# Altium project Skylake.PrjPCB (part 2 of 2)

## Sheet Skylake_TPS22993_U7.SchDoc
size 431 x 279 mm; Date: Not shown in title block; ApprovedBy: Not shown in title block; CheckedBy: Not shown in title block; Author: Not shown in title block; CompanyName: Not shown in title block; Engineer: Not shown in title block; Organization: Not shown in title block; Address1: Not shown in title block; Address2: Not shown in title block; Address3: Not shown in title block; Address4: Not shown in title block; DocumentNumber: 1; Revision: Use project parameter SCH_Rev; SheetNumber: 7; SheetTotal: 9; PageSetup: Record=PageOptions|CenterHorizontal=True|CenterVertical=True|PrintScale=1.00|XCorrection=1.00|YCorrection=1.00|PrintKind=0|BorderSize=5000000|LeftOffset=0|BottomOffset=0|Orientation=2|PaperLength=1000|PaperWidth=1000|Scale=100|PaperSource=15|PrintQuality=600|MediaType=1|DitherType=10|PaperKind=Letter|PrintScaleMode=1
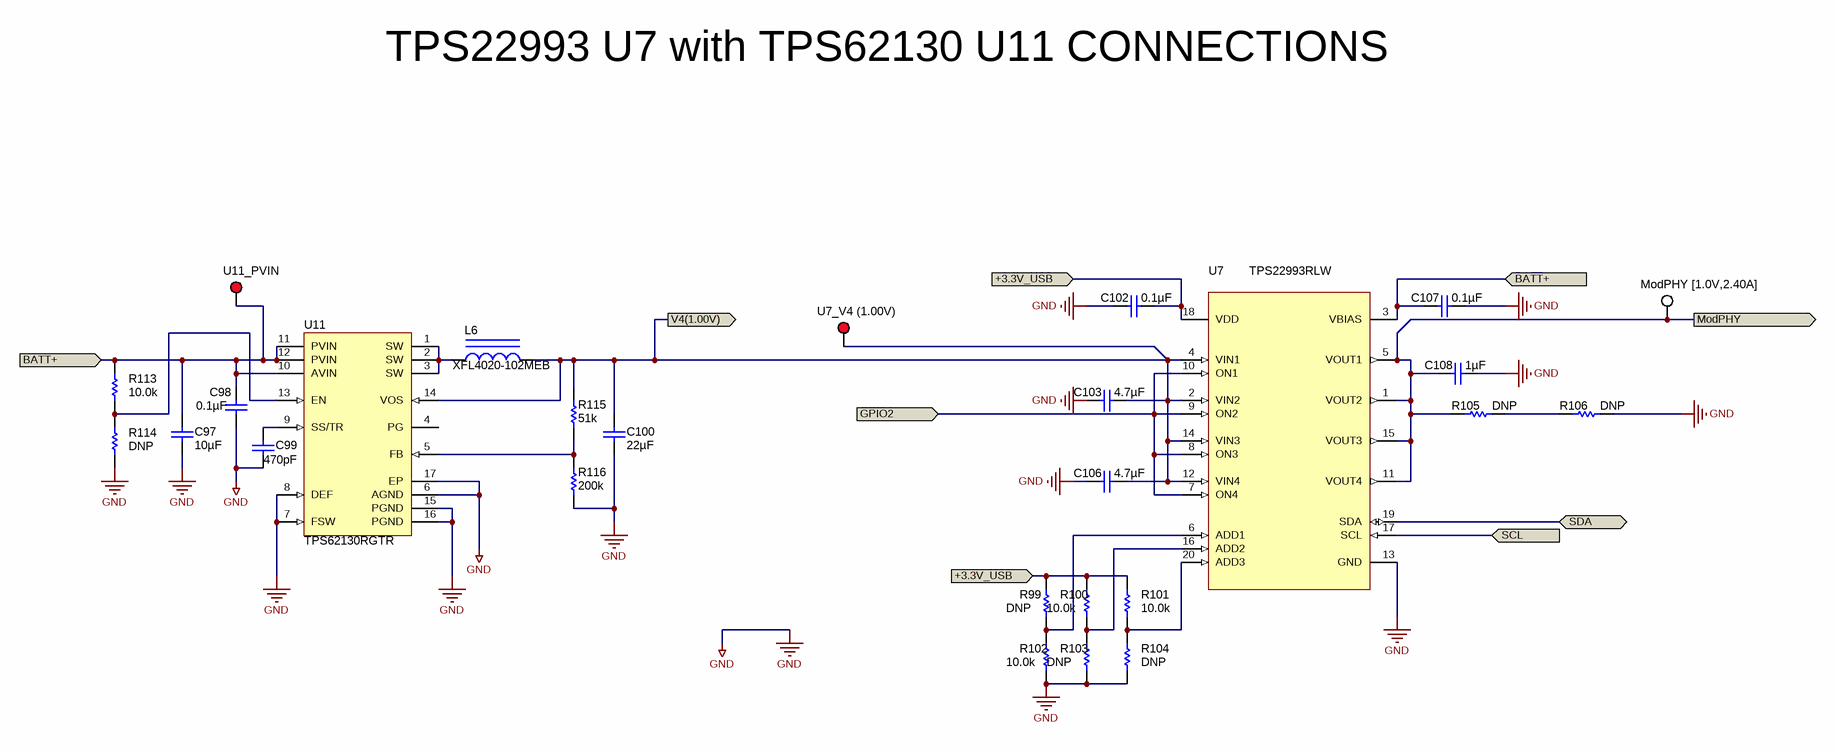
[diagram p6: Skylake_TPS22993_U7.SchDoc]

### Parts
C97  ValueDisplayed: 10µF  [0805_HV]  (hidden comment: C2012JB1V106K085AC)
C98  ValueDisplayed: 0.1µF  [0805_HV]  (hidden comment: 08055C104JAT2A)
C99  ValueDisplayed: 470pF  [0603]  (hidden comment: C0603C471K5RACTU)
C100  ValueDisplayed: 22µF  [0805_HV]  (hidden comment: LMK212BJ226MG-T)
C102  ValueDisplayed: 0.1µF  [0603]  (hidden comment: C0603C104K8RACTU)
C103  ValueDisplayed: 4.7µF  [0603]  (hidden comment: GRM188R60J475KE19D)
C106  ValueDisplayed: 4.7µF  [0603]  (hidden comment: GRM188R60J475KE19D)
C107  ValueDisplayed: 0.1µF  [0805_HV]  (hidden comment: GMK212BJ104KGHT)
C108  ValueDisplayed: 1µF  [0603]  (hidden comment: C0603C105K8PACTU)
L6  XFL4020-102MEB  [XFL4020]
ModPHY_[1.0V,2.40A]  5007  [Keystone5007]  (value not drawn)
R99  value DNP  [0402]  (hidden comment: CRCW040210K0FKED)
R100  value 10.0k  [0402]  (hidden comment: CRCW040210K0FKED)
R101  value 10.0k  [0402]  (hidden comment: CRCW040210K0FKED)
R102  value 10.0k  [0402]  (hidden comment: CRCW040210K0FKED)
R103  value DNP  [0402]  (hidden comment: CRCW040210K0FKED)
R104  value DNP  [0402]  (hidden comment: CRCW040210K0FKED)
R105  value DNP  [2512M]  (hidden comment: RLP73K3AR20JTE)
R106  value DNP  [2512M]  (hidden comment: RLP73K3AR22JTE)
R113  value 10.0k  [0402]  (hidden comment: CRCW040210K0FKED)
R114  value DNP  [0402]  (hidden comment: CRCW040210K0FKED)
R115  value 51k  [0603]  (hidden comment: CRCW060351K0JNEA)
R116  value 200k  [0603]  (hidden comment: CRCW0603200KFKEA)
U7  TPS22993RLW  [RLW0020A]
U7_V4_(1.00V)  5005  [Keystone5005]  (value not drawn)
U11  TPS62130RGTR  [RGT0016C]
U11_PVIN  5005  [Keystone5005]  (value not drawn)

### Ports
+3.3V_USB (in), BATT+ (in), GPIO2 (in), ModPHY (out), SCL (in), SDA (bidir), V4(1.00V) (out)

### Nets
GND: C97.2 C98.2 C99.2 C100.2 C102.2 C103.2 C106.2 C107.1 C108.1 R102.1 R103.1 R104.1 R106.2 R114.1 R116.1 U7.13(GND) U11.6(AGND) U11.7(FSW) U11.8(DEF) U11.15(PGND) U11.16(PGND) U11.17(EP)
+3.3V_USB: C102.1 R99.2 R100.2 R101.2 U7.18(VDD) ; port +3.3V_USB
BATT+: C97.1 C98.1 C107.2 R113.2 U7.3(VBIAS) U11.10(AVIN) U11.11(PVIN) U11.12(PVIN) U11_PVIN.1 ; port BATT+
GPIO2: U7.7(ON4) U7.8(ON3) U7.9(ON2) U7.10(ON1) ; port GPIO2
ModPHY: C108.2 ModPHY_[1.0V,2.40A].1 R105.1 U7.1(VOUT2) U7.5(VOUT1) U7.11(VOUT4) U7.15(VOUT3) ; port ModPHY
SCL: U7.17(SCL) ; port SCL
SDA: U7.19(SDA) ; port SDA
V4(1.00V): C100.1 C103.1 C106.1 L6.2 R115.2 U7.2(VIN2) U7.4(VIN1) U7.12(VIN4) U7.14(VIN3) U7_V4_(1.00V).1 U11.14(VOS) ; port V4(1.00V)
NetC99_1: C99.1 U11.9(SS/TR)
NetL6_1: L6.1 U11.1(SW) U11.2(SW) U11.3(SW)
NetR99_1: R99.1 R102.2 U7.6(ADD1)
NetR100_1: R100.1 R103.2 U7.16(ADD2)
NetR101_1: R101.1 R104.2 U7.20(ADD3)
NetR105_2: R105.2 R106.1
NetR113_1: R113.1 R114.2 U11.13(EN)
NetR115_1: R115.1 R116.2 U11.5(FB)

Not connected (* = marked no-connect by the designer): U11 4(PG)

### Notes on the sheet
- TPS22993 U7 with TPS62130 U11 CONNECTIONS

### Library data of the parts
C97 = GRM21BR61E226ME44: CAP, CERM, 10uF, 35V, +/-10%, X5R, 0805; Manufacturer: TDK Corporation; Polarized: N; CompType: Capacitor; U/M: EA; Cap_F: 0.000022; Tolerance_%: 20; Value1: Unknown; VDC_V: 35; TaMin_C: -55; TaMax_C: 85; Cap_Case: 0805
C98 = 08055C104JAT2A: CAP, CERM, 0.1uF, 50V, +/-5%, X7R, 0805; Manufacturer: AVX; Polarized: N; CompType: Capacitor; U/M: EA; Cap_F: 0.0000001; Tolerance_%: 5; ESR_Ohm: 0.024; Value1: 0.024 ohm; VDC_V: 50; TaMin_C: -55; TaMax_C: 125; Cap_Case: 0805
C99 = C0603C471K5RACTU: CAP, CERM, 470pF, 50V, +/-10%, X7R, 0603; Manufacturer: Kemet; Polarized: N; CompType: Capacitor; U/M: EA; Cap_F: 0.00000000047; Tolerance_%: 10; Value1: Unknown; VDC_V: 50; TaMin_C: -55; TaMax_C: 125
C100 = LMK212BJ226MG-T: CAP, CERM, 22uF, 10V, +/-20%, X5R, 0805; Manufacturer: Taiyo Yuden; Polarized: N; CompType: Capacitor; U/M: EA; Cap_F: 0.000022; Tolerance_%: 20; Value1: Unknown; VDC_V: 10; TaMin_C: -55; TaMax_C: 85; Cap_Case: 0805
C102 = GRM188R71C104KA01D: CAP, CERM, 0.1uF, 10V, +/-10%, X7R, 0603; Manufacturer: Kemet; Polarized: N; CompType: Capacitor; U/M: EA; Cap_F: 0.0000001; Tolerance_%: 10; Value1: Unknown; TaMin_C: -55; TaMax_C: 125
C103 C106 = GRM188R60J475KE19D: CAP, CERM, 4.7uF, 6.3V, +/-10%, X5R, 0603; Manufacturer: MuRata; Polarized: N; CompType: Capacitor; U/M: EA; Cap_F: 0.0000047; Tolerance_%: 10; ESR_Ohm: 0.005; Value1: 0.005 ohm; VDC_V: 6.3; IRMS_A: 2; TaMin_C: -55; TaMax_C: 85
C107 = GRM21BR61E226ME44: CAP, CERM, 0.1uF, 35V, +/-20%, X5R, 0805; Manufacturer: Taiyo Yuden; Polarized: N; CompType: Capacitor; U/M: EA; Cap_F: 0.000022; Tolerance_%: 20; Value1: Unknown; VDC_V: 35; TaMin_C: -55; TaMax_C: 85; Cap_Case: 0805
C108 = C0603C105K8PACTU: CAP, CERM, 1uF, 10V, +/-10%, X5R, 0603; Manufacturer: Kemet; Polarized: N; CompType: Capacitor; U/M: EA; Cap_F: 0.000001; Tolerance_%: 10; Value1: Unknown; TaMin_C: -55; TaMax_C: 85
L6 = XFL4020-102MEB: Inductor, Shielded, Composite, 1uH, 5.4A, 0.01 ohm, SMD; Manufacturer: Coilcraft; Ind_H: 1.0E-6; ValueDisplayed: 1µH; Imax_A: 5.4; Irms: 11A @ 40C rise; Isat: 5.4A @ 30% inductance drop; DCR_ohm: 0.01; U/M: EA
ModPHY_[1.0V,2.40A] = 5007: Test Point, Compact, White, TH; Manufacturer: Keystone; CompType: Test Point Loop; U/M: EA
R99 R103 R104 R114 = CRCW040210K0FKED: RES, DNP, 1%, 0.063W, 0402; Manufacturer: Vishay-Dale; CompType: Resistor; Res_ohm: 10000; Value_Code: 10k0; Tolerance_%: 1; Power_W: 0.063; VDC_V: 50; TempCo: 100 ppm/C; EIA_Code: E96; U/M: EA
R100-R102 R113 = CRCW040210K0FKED: RES, 10.0k ohm, 1%, 0.063W, 0402; Manufacturer: Vishay-Dale; CompType: Resistor; Res_ohm: 10000; Value_Code: 10k0; Tolerance_%: 1; Power_W: 0.063; VDC_V: 50; TempCo: 100 ppm/C; EIA_Code: E96; U/M: EA
R105 R106 = CRCW25121K10JNEG: RES, DNP, 5%, 2W, 2512; Manufacturer: TE Connectivity; CompType: Resistor; Tolerance_%: 5; Power_W: 1; VDC_V: 500; TempCo: 200 ppm/C; EIA_Code: E24; U/M: EA
R115 = CRCW060351K0JNEA: RES, 51k ohm, 5%, 0.1W, 0603; Manufacturer: Vishay-Dale; CompType: Resistor; Res_ohm: 51000; Value_Code: 51k0; Tolerance_%: 5; Power_W: 0.1; VDC_V: 75; TempCo: 200 ppm/C; EIA_Code: E24; U/M: EA
R116 = CRCW0603200KFKEA: RES, 200k ohm, 1%, 0.1W, 0603; Manufacturer: Vishay-Dale; CompType: Resistor; Res_ohm: 200000; Tolerance_%: 1; Power_W: 0.1; VDC_V: 75; TempCo: 100 ppm/C; EIA_Code: E96; U/M: EA
U7 = TPS22993RLW: Quad Channel Load Switch with GPIO and I2C Control, RLW0020A; Alternate Manufacturer: None; Manufacturer: Texas Instruments; SymbolCreator: a0411947; CompType: IC; U/M: EA
U7_V4_(1.00V) U11_PVIN = 5005: Test Point, Compact, Red, TH; Manufacturer: Keystone; CompType: Test Point Loop; U/M: EA
U11 = TPS62130RGTR: Buck Step Down Regulator with 3 to 17 V Input and 0.9 to 6 V Output, -40 to 85 degC, 16-Pin QFN (RGT), Green (RoHS & no Sb/Br); Manufacturer: Texas Instruments; Alternate Manufacturer: None; Alternate PartNumber: Equivalent; Duty Cycle(Max)(%): 100; Iout(Max)(A): 3; Iq(Typ)(mA): 0.017; Rating: Catalog; Regulated Outputs(#): 1; SubFamily: Step-Down Regulator; Switch Current Limit(Typ)(A): 4.2; Synchronous Rectification: TRUE; Vin(Max)(V): 17; Vout(Max)(V): 6; Vout(Min)(V): 0.9

## Sheet Skylake_LEDs_1.SchDoc
size 431 x 279 mm; Date: Not shown in title block; ApprovedBy: Not shown in title block; CheckedBy: Not shown in title block; Author: Not shown in title block; CompanyName: Not shown in title block; Engineer: Not shown in title block; Organization: Not shown in title block; Address1: Not shown in title block; Address2: Not shown in title block; Address3: Not shown in title block; Address4: Not shown in title block; DocumentNumber: 1; Revision: Use project parameter SCH_Rev; SheetNumber: 8; SheetTotal: 9; PageSetup: Record=PageOptions|CenterHorizontal=True|CenterVertical=True|PrintScale=1.00|XCorrection=1.00|YCorrection=1.00|PrintKind=0|BorderSize=5000000|LeftOffset=0|BottomOffset=0|Orientation=2|PaperLength=1000|PaperWidth=1000|Scale=100|PaperSource=15|PrintQuality=600|MediaType=1|DitherType=10|PaperKind=Letter|PrintScaleMode=1
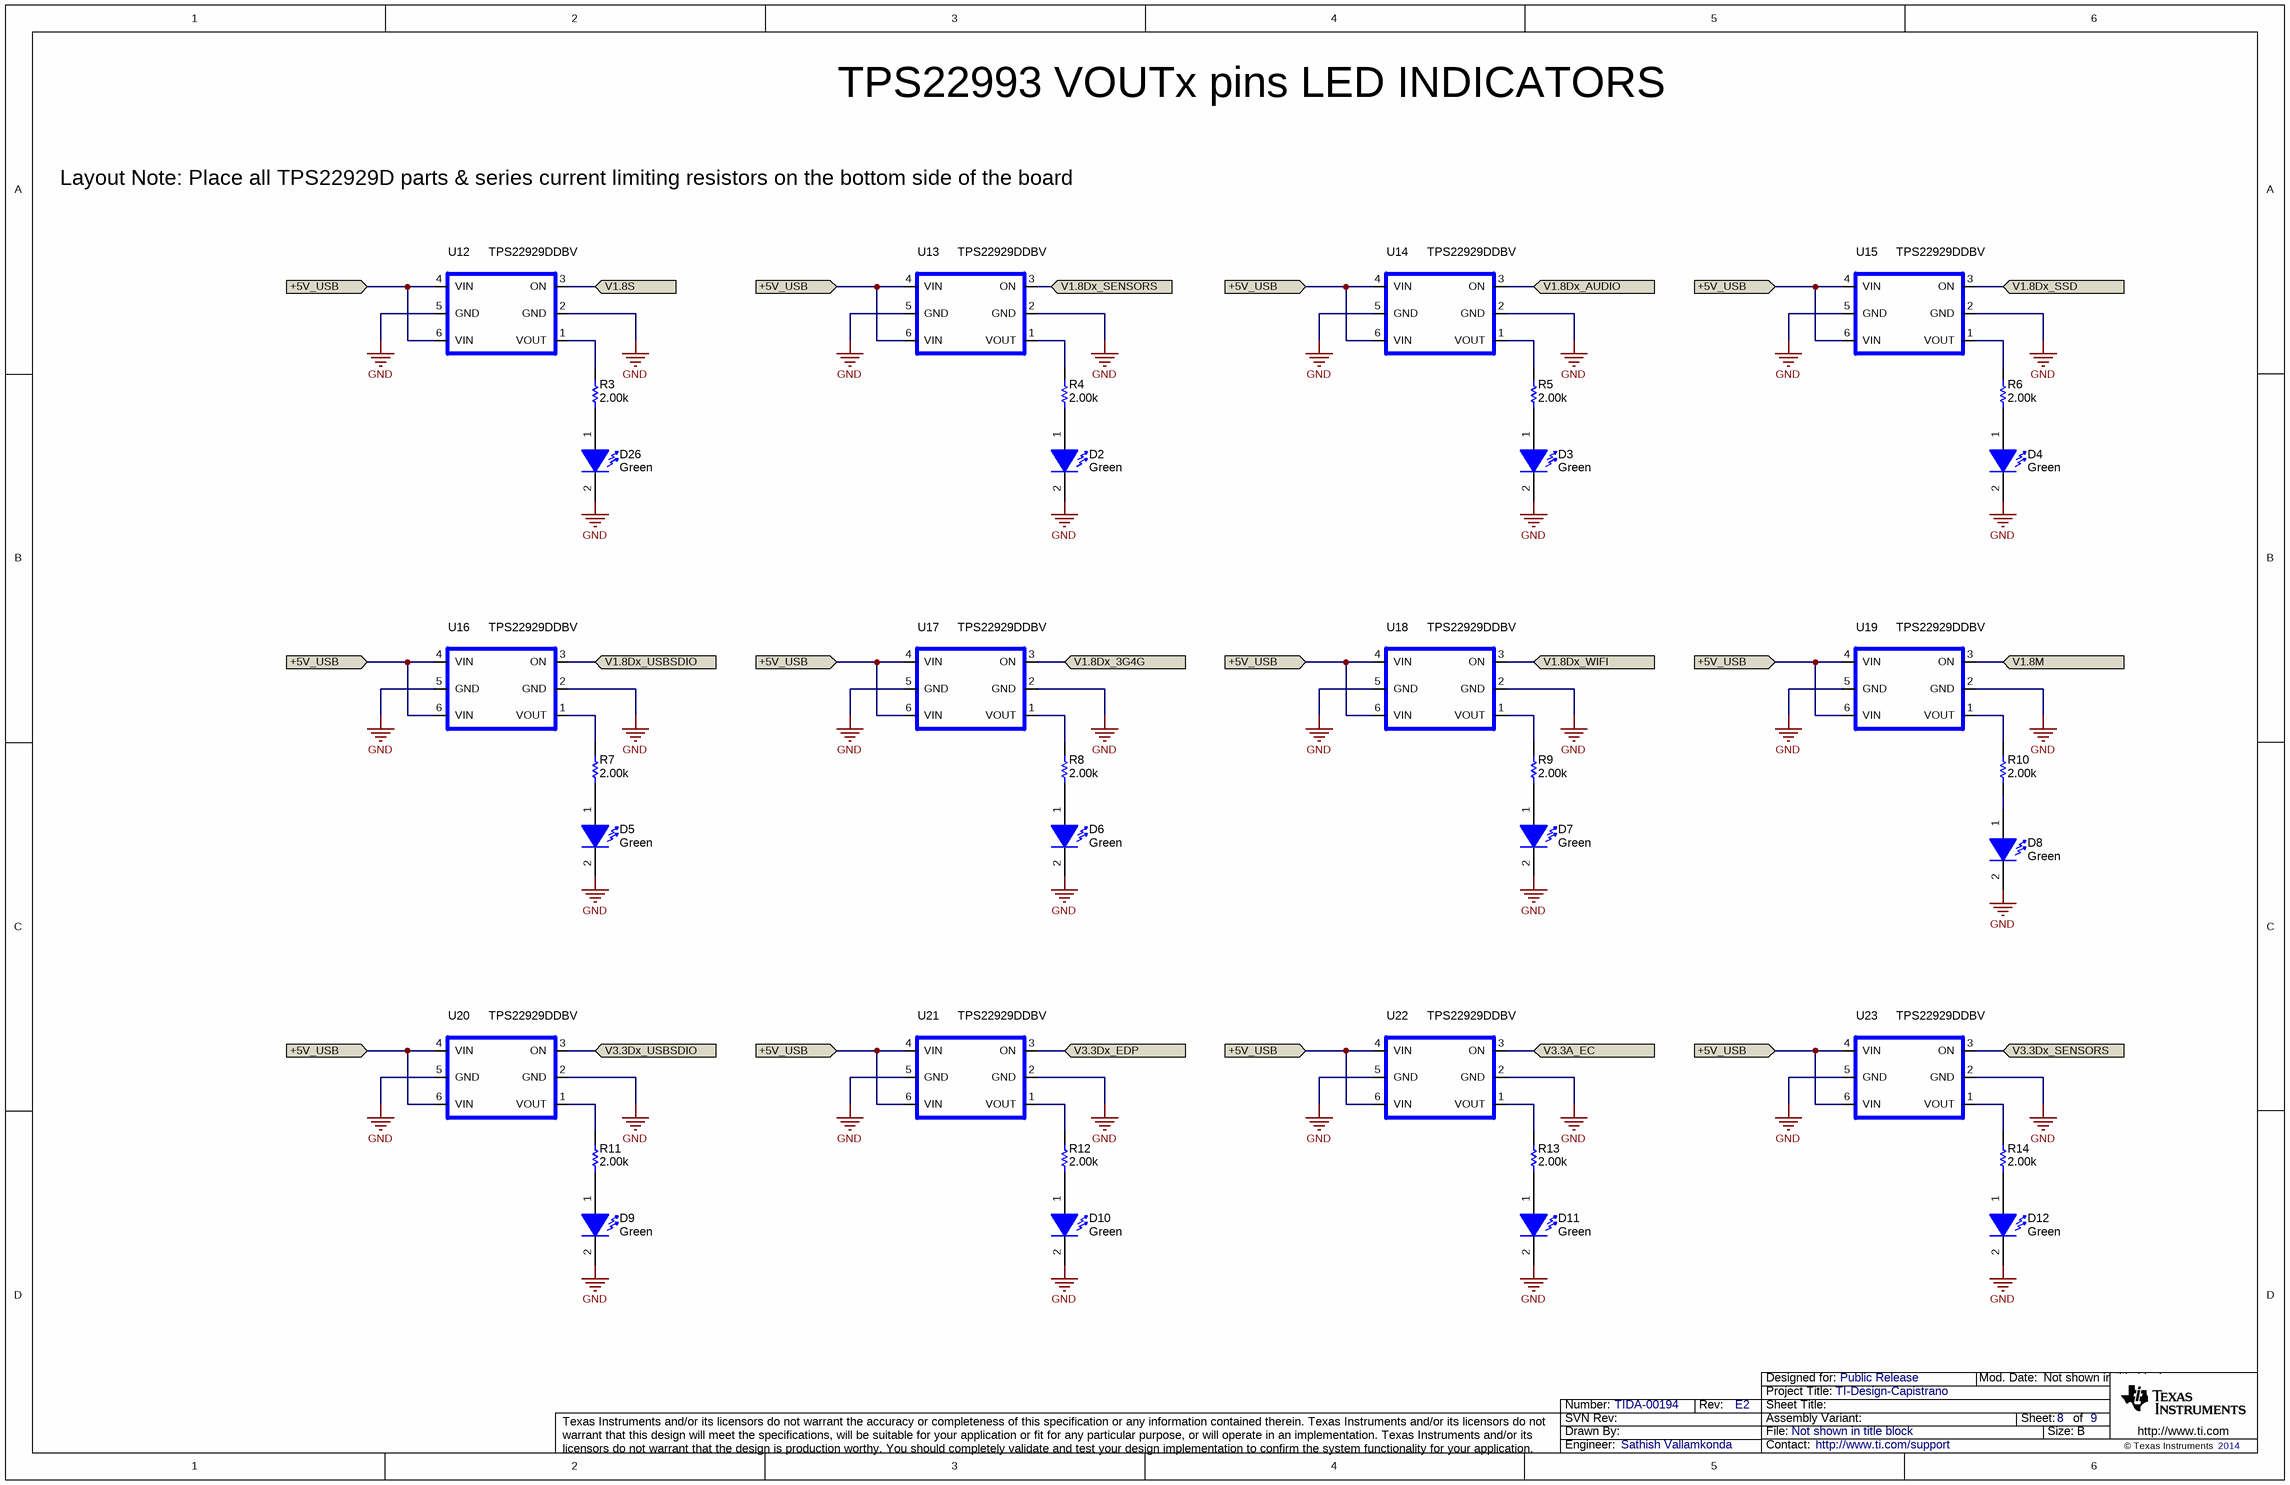
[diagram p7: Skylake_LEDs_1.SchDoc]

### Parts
D2  value Green  [LED_SML]  (hidden comment: SML312ECTT86)
D3  value Green  [LED_SML]  (hidden comment: SML312ECTT86)
D4  value Green  [LED_SML]  (hidden comment: SML312ECTT86)
D5  value Green  [LED_SML]  (hidden comment: SML312ECTT86)
D6  value Green  [LED_SML]  (hidden comment: SML312ECTT86)
D7  value Green  [LED_SML]  (hidden comment: SML312ECTT86)
D8  value Green  [LED_SML]  (hidden comment: SML312ECTT86)
D9  value Green  [LED_SML]  (hidden comment: SML312ECTT86)
D10  value Green  [LED_SML]  (hidden comment: SML312ECTT86)
D11  value Green  [LED_SML]  (hidden comment: SML312ECTT86)
D12  value Green  [LED_SML]  (hidden comment: SML312ECTT86)
D26  value Green  [LED_SML]  (hidden comment: SML312ECTT86)
R3  value 2.00k  [0603]  (hidden comment: CRCW06032K00FKEA)
R4  value 2.00k  [0603]  (hidden comment: CRCW06032K00FKEA)
R5  value 2.00k  [0603]  (hidden comment: CRCW06032K00FKEA)
R6  value 2.00k  [0603]  (hidden comment: CRCW06032K00FKEA)
R7  value 2.00k  [0603]  (hidden comment: CRCW06032K00FKEA)
R8  value 2.00k  [0603]  (hidden comment: CRCW06032K00FKEA)
R9  value 2.00k  [0603]  (hidden comment: CRCW06032K00FKEA)
R10  value 2.00k  [0603]  (hidden comment: CRCW06032K00FKEA)
R11  value 2.00k  [0603]  (hidden comment: CRCW06032K00FKEA)
R12  value 2.00k  [0603]  (hidden comment: CRCW06032K00FKEA)
R13  value 2.00k  [0603]  (hidden comment: CRCW06032K00FKEA)
R14  value 2.00k  [0603]  (hidden comment: CRCW06032K00FKEA)
U12  TPS22929DDBV  [DBV-6]
U13  TPS22929DDBV  [DBV-6]
U14  TPS22929DDBV  [DBV-6]
U15  TPS22929DDBV  [DBV-6]
U16  TPS22929DDBV  [DBV-6]
U17  TPS22929DDBV  [DBV-6]
U18  TPS22929DDBV  [DBV-6]
U19  TPS22929DDBV  [DBV-6]
U20  TPS22929DDBV  [DBV-6]
U21  TPS22929DDBV  [DBV-6]
U22  TPS22929DDBV  [DBV-6]
U23  TPS22929DDBV  [DBV-6]

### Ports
+5V_USB (in), V1.8Dx_3G4G (in), V1.8Dx_AUDIO (in), V1.8Dx_SENSORS (in), V1.8Dx_SSD (in), V1.8Dx_USBSDIO (in), V1.8Dx_WIFI (in), V1.8M (in), V1.8S (in), V3.3A_EC (in), V3.3Dx_EDP (in), V3.3Dx_SENSORS (in), V3.3Dx_USBSDIO (in)

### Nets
GND: D2.2(K) D3.2(K) D4.2(K) D5.2(K) D6.2(K) D7.2(K) D8.2(K) D9.2(K) D10.2(K) D11.2(K) D12.2(K) D26.2(K) U12.2(GND) U12.5(GND) U13.2(GND) U13.5(GND) U14.2(GND) U14.5(GND) U15.2(GND) U15.5(GND) U16.2(GND) U16.5(GND) U17.2(GND) U17.5(GND) U18.2(GND) U18.5(GND) U19.2(GND) U19.5(GND) U20.2(GND) U20.5(GND) U21.2(GND) U21.5(GND) U22.2(GND) U22.5(GND) U23.2(GND) U23.5(GND)
+5V_USB: U12.4(VIN) U12.6(VIN) U13.4(VIN) U13.6(VIN) U14.4(VIN) U14.6(VIN) U15.4(VIN) U15.6(VIN) U16.4(VIN) U16.6(VIN) U17.4(VIN) U17.6(VIN) U18.4(VIN) U18.6(VIN) U19.4(VIN) U19.6(VIN) U20.4(VIN) U20.6(VIN) U21.4(VIN) U21.6(VIN) U22.4(VIN) U22.6(VIN) U23.4(VIN) U23.6(VIN) ; port +5V_USB
V1.8Dx_3G4G: U17.3(ON) ; port V1.8Dx_3G4G
V1.8Dx_AUDIO: U14.3(ON) ; port V1.8Dx_AUDIO
V1.8Dx_SENSORS: U13.3(ON) ; port V1.8Dx_SENSORS
V1.8Dx_SSD: U15.3(ON) ; port V1.8Dx_SSD
V1.8Dx_USBSDIO: U16.3(ON) ; port V1.8Dx_USBSDIO
V1.8Dx_WIFI: U18.3(ON) ; port V1.8Dx_WIFI
V1.8M: U19.3(ON) ; port V1.8M
V1.8S: U12.3(ON) ; port V1.8S
V3.3A_EC: U22.3(ON) ; port V3.3A_EC
V3.3Dx_EDP: U21.3(ON) ; port V3.3Dx_EDP
V3.3Dx_SENSORS: U23.3(ON) ; port V3.3Dx_SENSORS
V3.3Dx_USBSDIO: U20.3(ON) ; port V3.3Dx_USBSDIO
NetD2_1: D2.1(A) R4.1
NetD3_1: D3.1(A) R5.1
NetD4_1: D4.1(A) R6.1
NetD5_1: D5.1(A) R7.1
NetD6_1: D6.1(A) R8.1
NetD7_1: D7.1(A) R9.1
NetD8_1: D8.1(A) R10.1
NetD9_1: D9.1(A) R11.1
NetD10_1: D10.1(A) R12.1
NetD11_1: D11.1(A) R13.1
NetD12_1: D12.1(A) R14.1
NetD26_1: D26.1(A) R3.1
NetR3_2: R3.2 U12.1(VOUT)
NetR4_2: R4.2 U13.1(VOUT)
NetR5_2: R5.2 U14.1(VOUT)
NetR6_2: R6.2 U15.1(VOUT)
NetR7_2: R7.2 U16.1(VOUT)
NetR8_2: R8.2 U17.1(VOUT)
NetR9_2: R9.2 U18.1(VOUT)
NetR10_2: R10.2 U19.1(VOUT)
NetR11_2: R11.2 U20.1(VOUT)
NetR12_2: R12.2 U21.1(VOUT)
NetR13_2: R13.2 U22.1(VOUT)
NetR14_2: R14.2 U23.1(VOUT)

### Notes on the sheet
- TPS22993 VOUTx pins LED INDICATORS
- Layout Note: Place all TPS22929D parts & series current limiting resistors on the bottom side of the board

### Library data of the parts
D2-D12 D26 = SML312WBCW1: LED, Green, SMD; Manufacturer: Rohm; Type: AlInGaP; ColorTemperature: 8000K; Vf_V: 3; Value2: 3V; Io_A: 0.005; Value1: W; U/M: EA
R3-R14 = CRCW06032K00FKEA: RES, 2.00k ohm, 1%, 0.1W, 0603; Manufacturer: Vishay-Dale; CompType: Resistor; Res_ohm: 2000; Value_Code: 2k00; Tolerance_%: 1; Power_W: 0.1; VDC_V: 75; TempCo: 100 ppm/C; EIA_Code: E96; U/M: EA
U12-U23 = TPS2292XDBV: IC, LOW INPUT VOLTAGE LOAD SWITCH  WITH CONTROLLED TURN-ON; Manufacturer: TI; Alternate Manufacturer: None; Area: 18.50 mm; Value: TPS22929DBV

## Sheet Skylake_LEDs_2.SchDoc
size 431 x 279 mm; Date: Not shown in title block; ApprovedBy: Not shown in title block; CheckedBy: Not shown in title block; Author: Not shown in title block; CompanyName: Not shown in title block; Engineer: Not shown in title block; Organization: Not shown in title block; Address1: Not shown in title block; Address2: Not shown in title block; Address3: Not shown in title block; Address4: Not shown in title block; DocumentNumber: 1; Revision: Use project parameter SCH_Rev; SheetNumber: 9; SheetTotal: 9; PageSetup: Record=PageOptions|CenterHorizontal=True|CenterVertical=True|PrintScale=1.00|XCorrection=1.00|YCorrection=1.00|PrintKind=0|BorderSize=5000000|LeftOffset=0|BottomOffset=0|Orientation=2|PaperLength=1000|PaperWidth=1000|Scale=100|PaperSource=15|PrintQuality=600|MediaType=1|DitherType=10|PaperKind=Letter|PrintScaleMode=1
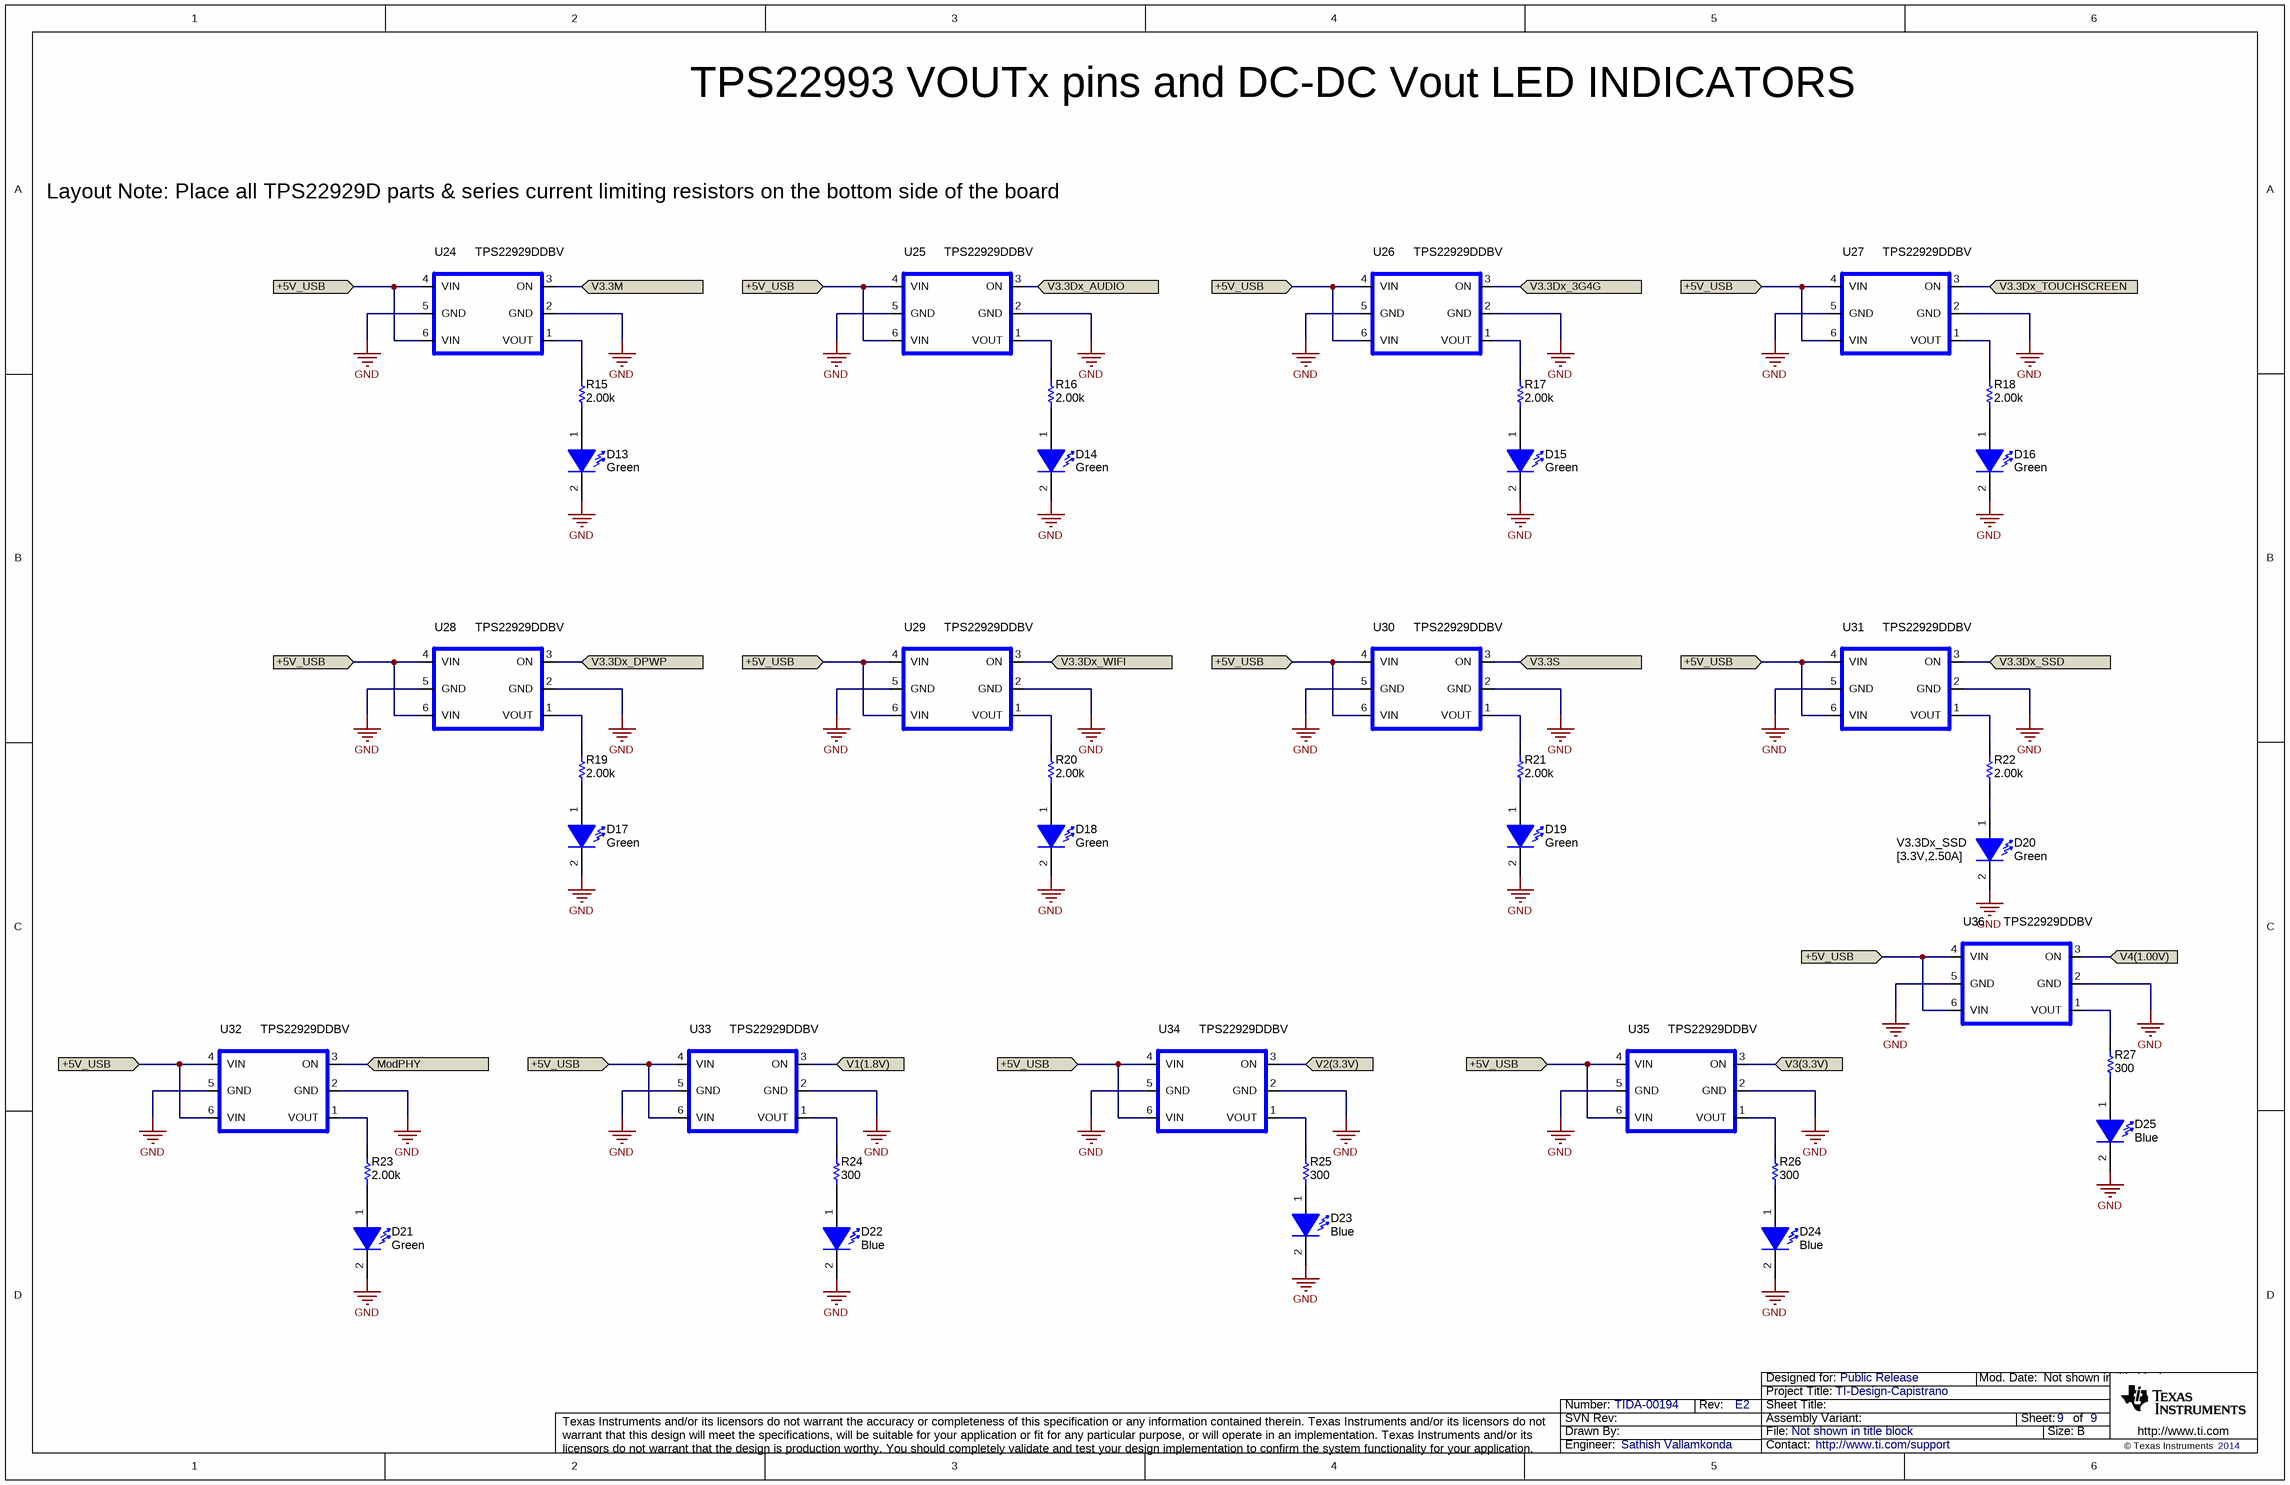
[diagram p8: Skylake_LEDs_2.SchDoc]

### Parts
D13  value Green  [LED_SML]  (hidden comment: SML312ECTT86)
D14  value Green  [LED_SML]  (hidden comment: SML312ECTT86)
D15  value Green  [LED_SML]  (hidden comment: SML312ECTT86)
D16  value Green  [LED_SML]  (hidden comment: SML312ECTT86)
D17  value Green  [LED_SML]  (hidden comment: SML312ECTT86)
D18  value Green  [LED_SML]  (hidden comment: SML312ECTT86)
D19  value Green  [LED_SML]  (hidden comment: SML312ECTT86)
D20  value Green  [LED_SML]  (hidden comment: SML312ECTT86)
D21  value Green  [LED_SML]  (hidden comment: SML312ECTT86)
D22  value Blue  [LED_SML]  (hidden comment: SML312BCTT86)
D23  value Blue  [LED_SML]  (hidden comment: SML312BCTT86)
D24  value Blue  [LED_SML]  (hidden comment: SML312BCTT86)
D25  value Blue  [LED_SML]  (hidden comment: SML312BCTT86)
R15  value 2.00k  [0603]  (hidden comment: CRCW06032K00FKEA)
R16  value 2.00k  [0603]  (hidden comment: CRCW06032K00FKEA)
R17  value 2.00k  [0603]  (hidden comment: CRCW06032K00FKEA)
R18  value 2.00k  [0603]  (hidden comment: CRCW06032K00FKEA)
R19  value 2.00k  [0603]  (hidden comment: CRCW06032K00FKEA)
R20  value 2.00k  [0603]  (hidden comment: CRCW06032K00FKEA)
R21  value 2.00k  [0603]  (hidden comment: CRCW06032K00FKEA)
R22  value 2.00k  [0603]  (hidden comment: CRCW06032K00FKEA)
R23  value 2.00k  [0603]  (hidden comment: CRCW06032K00FKEA)
R24  value 300  [0603]  (hidden comment: CRCW0603300RJNEA)
R25  value 300  [0603]  (hidden comment: CRCW0603300RJNEA)
R26  value 300  [0603]  (hidden comment: CRCW0603300RJNEA)
R27  value 300  [0603]  (hidden comment: CRCW0603300RJNEA)
U24  TPS22929DDBV  [DBV-6]
U25  TPS22929DDBV  [DBV-6]
U26  TPS22929DDBV  [DBV-6]
U27  TPS22929DDBV  [DBV-6]
U28  TPS22929DDBV  [DBV-6]
U29  TPS22929DDBV  [DBV-6]
U30  TPS22929DDBV  [DBV-6]
U31  TPS22929DDBV  [DBV-6]
U32  TPS22929DDBV  [DBV-6]
U33  TPS22929DDBV  [DBV-6]
U34  TPS22929DDBV  [DBV-6]
U35  TPS22929DDBV  [DBV-6]
U36  TPS22929DDBV  [DBV-6]

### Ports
+5V_USB (in), ModPHY (in), V1(1.8V) (in), V2(3.3V) (in), V3(3.3V) (in), V3.3Dx_3G4G (in), V3.3Dx_AUDIO (in), V3.3Dx_DPWP (in), V3.3Dx_SSD (in), V3.3Dx_TOUCHSCREEN (in), V3.3Dx_WIFI (in), V3.3M (in), V3.3S (in), V4(1.00V) (in)

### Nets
GND: D13.2(K) D14.2(K) D15.2(K) D16.2(K) D17.2(K) D18.2(K) D19.2(K) D20.2(K) D21.2(K) D22.2(K) D23.2(K) D24.2(K) D25.2(K) U24.2(GND) U24.5(GND) U25.2(GND) U25.5(GND) U26.2(GND) U26.5(GND) U27.2(GND) U27.5(GND) U28.2(GND) U28.5(GND) U29.2(GND) U29.5(GND) U30.2(GND) U30.5(GND) U31.2(GND) U31.5(GND) U32.2(GND) U32.5(GND) U33.2(GND) U33.5(GND) U34.2(GND) U34.5(GND) U35.2(GND) U35.5(GND) U36.2(GND) U36.5(GND)
+5V_USB: U24.4(VIN) U24.6(VIN) U25.4(VIN) U25.6(VIN) U26.4(VIN) U26.6(VIN) U27.4(VIN) U27.6(VIN) U28.4(VIN) U28.6(VIN) U29.4(VIN) U29.6(VIN) U30.4(VIN) U30.6(VIN) U31.4(VIN) U31.6(VIN) U32.4(VIN) U32.6(VIN) U33.4(VIN) U33.6(VIN) U34.4(VIN) U34.6(VIN) U35.4(VIN) U35.6(VIN) U36.4(VIN) U36.6(VIN) ; port +5V_USB
ModPHY: U32.3(ON) ; port ModPHY
V1(1.8V): U33.3(ON) ; port V1(1.8V)
V2(3.3V): U34.3(ON) ; port V2(3.3V)
V3(3.3V): U35.3(ON) ; port V3(3.3V)
V3.3Dx_3G4G: U26.3(ON) ; port V3.3Dx_3G4G
V3.3Dx_AUDIO: U25.3(ON) ; port V3.3Dx_AUDIO
V3.3Dx_DPWP: U28.3(ON) ; port V3.3Dx_DPWP
V3.3Dx_SSD: U31.3(ON) ; port V3.3Dx_SSD
V3.3Dx_TOUCHSCREEN: U27.3(ON) ; port V3.3Dx_TOUCHSCREEN
V3.3Dx_WIFI: U29.3(ON) ; port V3.3Dx_WIFI
V3.3M: U24.3(ON) ; port V3.3M
V3.3S: U30.3(ON) ; port V3.3S
V4(1.00V): U36.3(ON) ; port V4(1.00V)
NetD13_1: D13.1(A) R15.1
NetD14_1: D14.1(A) R16.1
NetD15_1: D15.1(A) R17.1
NetD16_1: D16.1(A) R18.1
NetD17_1: D17.1(A) R19.1
NetD18_1: D18.1(A) R20.1
NetD19_1: D19.1(A) R21.1
NetD20_1: D20.1(A) R22.1
NetD21_1: D21.1(A) R23.1
NetD22_1: D22.1(A) R24.1
NetD23_1: D23.1(A) R25.1
NetD24_1: D24.1(A) R26.1
NetD25_1: D25.1(A) R27.1
NetR15_2: R15.2 U24.1(VOUT)
NetR16_2: R16.2 U25.1(VOUT)
NetR17_2: R17.2 U26.1(VOUT)
NetR18_2: R18.2 U27.1(VOUT)
NetR19_2: R19.2 U28.1(VOUT)
NetR20_2: R20.2 U29.1(VOUT)
NetR21_2: R21.2 U30.1(VOUT)
NetR22_2: R22.2 U31.1(VOUT)
NetR23_2: R23.2 U32.1(VOUT)
NetR24_2: R24.2 U33.1(VOUT)
NetR25_2: R25.2 U34.1(VOUT)
NetR26_2: R26.2 U35.1(VOUT)
NetR27_2: R27.2 U36.1(VOUT)

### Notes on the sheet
- TPS22993 VOUTx pins and DC-DC Vout LED INDICATORS
- Layout Note: Place all TPS22929D parts & series current limiting resistors on the bottom side of the board
- (near D20) V3.3Dx_SSD
  [3.3V,2.50A]

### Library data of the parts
D13-D21 = SML312WBCW1: as D2 on sheet Skylake_LEDs_1
D22-D25 = SML312WBCW1: LED, Blue, SMD; Manufacturer: Rohm; Type: AlInGaP; ColorTemperature: 8000K; Vf_V: 3; Value2: 3V; Io_A: 0.005; Value1: W; U/M: EA
R15-R23 = CRCW06032K00FKEA: as R3 on sheet Skylake_LEDs_1
R24-R27 = CRCW0603300RJNEA: RES, 300 ohm, 5%, 0.1W, 0603; Manufacturer: Vishay-Dale; CompType: Resistor; Value_Code: 300R; Tolerance_%: 5; Power_W: 0.1; VDC_V: 75; TempCo: 200 ppm/C; EIA_Code: E24; U/M: EA
U24-U36 = TPS2292XDBV: as U12 on sheet Skylake_LEDs_1

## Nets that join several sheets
GND: Skylake_Hardware (35 pins), Skylake_USB2ANY_connections (8 pins), Skylake_TPS22993_U1_U2 (43 pins), Skylake_TPS22993_U3_U4 (44 pins), Skylake_TPS22993_U5_U6 (40 pins), Skylake_TPS22993_U7 (22 pins), Skylake_LEDs_1 (36 pins), Skylake_LEDs_2 (39 pins)
+3.3V_USB: Skylake_Hardware (C15.1 C16.1 C17.1 C18.1), Skylake_USB2ANY_connections (5 pins), Skylake_TPS22993_U1_U2 (10 pins), Skylake_TPS22993_U3_U4 (10 pins), Skylake_TPS22993_U5_U6 (10 pins), Skylake_TPS22993_U7 (5 pins)
+5V_USB: Skylake_Hardware (8 pins), Skylake_USB2ANY_connections (+5V_USB.1 C19.1 J15.1), Skylake_LEDs_1 (24 pins), Skylake_LEDs_2 (26 pins)
BATT+: Skylake_Hardware (9 pins), Skylake_TPS22993_U1_U2 (11 pins), Skylake_TPS22993_U3_U4 (14 pins), Skylake_TPS22993_U5_U6 (14 pins), Skylake_TPS22993_U7 (9 pins)
GPIO2: Skylake_USB2ANY_connections (GPIO2.1 J1.17), Skylake_TPS22993_U7 (U7.7 U7.8 U7.9 U7.10)
GPIO3: Skylake_USB2ANY_connections (GPIO3.1 J1.18), Skylake_TPS22993_U1_U2 (U1.7 U1.10 U2.7), Skylake_TPS22993_U3_U4 (U3.8 U3.9 U4.10), Skylake_TPS22993_U5_U6 (U6.7 U6.8 U6.9 U6.10)
GPIO4: Skylake_USB2ANY_connections (GPIO4.1 J1.13), Skylake_TPS22993_U1_U2 (U2.8 U2.9), Skylake_TPS22993_U3_U4 (U4.7 U4.8), Skylake_TPS22993_U5_U6 (U5.7 U5.8)
GPIO5: Skylake_USB2ANY_connections (GPIO5.1 J1.14), Skylake_TPS22993_U1_U2 (U1.8), Skylake_TPS22993_U3_U4 (U4.9)
GPIO6: Skylake_USB2ANY_connections (GPIO6.1 J1.11), Skylake_TPS22993_U1_U2 (U1.9), Skylake_TPS22993_U3_U4 (U3.7)
GPIO8: Skylake_USB2ANY_connections (GPIO8.1 J1.25), Skylake_TPS22993_U1_U2 (U2.10), Skylake_TPS22993_U3_U4 (U3.10)
GPIO9: Skylake_USB2ANY_connections (GPIO9.1 J1.26), Skylake_TPS22993_U5_U6 (U5.10)
GPIO10: Skylake_USB2ANY_connections (GPIO10.1 J1.29), Skylake_TPS22993_U5_U6 (U5.9)
ModPHY: Skylake_TPS22993_U7 (7 pins), Skylake_LEDs_2 (U32.3)
SCL: Skylake_USB2ANY_connections (J1.20 R1.1 SCL.1), Skylake_TPS22993_U1_U2 (U1.17 U2.17), Skylake_TPS22993_U3_U4 (U3.17 U4.17), Skylake_TPS22993_U5_U6 (U5.17 U6.17), Skylake_TPS22993_U7 (U7.17)
SDA: Skylake_USB2ANY_connections (J1.19 R2.1 SDA.1), Skylake_TPS22993_U1_U2 (U1.19 U2.19), Skylake_TPS22993_U3_U4 (U3.19 U4.19), Skylake_TPS22993_U5_U6 (U5.19 U6.19), Skylake_TPS22993_U7 (U7.19)
V1(1.8V): Skylake_TPS22993_U1_U2 (18 pins), Skylake_LEDs_2 (U33.3)
V1.8Dx_3G4G: Skylake_TPS22993_U1_U2 (C43.2 R46.1 U2.1 V1.8Dx_3G4G_[1.8V,0.07A].1), Skylake_LEDs_1 (U17.3)
V1.8Dx_AUDIO: Skylake_TPS22993_U1_U2 (C34.2 R37.1 U1.15 V1.8Dx_AUDIO_[1.8V,0.13A].1), Skylake_LEDs_1 (U14.3)
V1.8Dx_SENSORS: Skylake_TPS22993_U1_U2 (C33.2 R36.1 U1.1 V1.8Dx_SENSORS_[1.8V,0.07A].1), Skylake_LEDs_1 (U13.3)
V1.8Dx_SSD: Skylake_TPS22993_U1_U2 (C35.2 R38.1 U1.11 V1.8Dx_SSD_[1.8V,0.07A].1), Skylake_LEDs_1 (U15.3)
V1.8Dx_USBSDIO: Skylake_TPS22993_U1_U2 (C42.2 R45.1 U2.5 V1.8Dx_USBSDIO_[1.8V,0.05A].1), Skylake_LEDs_1 (U16.3)
V1.8Dx_WIFI: Skylake_TPS22993_U1_U2 (C44.2 R47.1 U2.15 V1.8Dx_WIFI_[1.8V,0.07A].1), Skylake_LEDs_1 (U18.3)
V1.8M: Skylake_TPS22993_U1_U2 (C45.2 R48.1 U2.11 V1.8M_[1.8V,0.01A].1), Skylake_LEDs_1 (U19.3)
V1.8S: Skylake_TPS22993_U1_U2 (C32.2 R35.1 U1.5 V1.8S_[1.8V,0.10A].1), Skylake_LEDs_1 (U12.3)
V2(3.3V): Skylake_TPS22993_U3_U4 (19 pins), Skylake_LEDs_2 (U34.3)
V3(3.3V): Skylake_TPS22993_U5_U6 (19 pins), Skylake_LEDs_2 (U35.3)
V3.3A_EC: Skylake_TPS22993_U3_U4 (C60.2 R60.1 U3.15 V3.3A_EC_[3.3V,0.10A].1), Skylake_LEDs_1 (U22.3)
V3.3Dx_3G4G: Skylake_TPS22993_U3_U4 (5 pins), Skylake_LEDs_2 (U26.3)
V3.3Dx_AUDIO: Skylake_TPS22993_U3_U4 (C69.2 R69.1 U4.1 V3.3Dx_AUDIO_[3.3V,0.20A].1), Skylake_LEDs_2 (U25.3)
V3.3Dx_DPWP: Skylake_TPS22993_U5_U6 (C85.2 R82.1 U5.1 V3.3Dx_DPWP_[3.3V,0.50A].1), Skylake_LEDs_2 (U28.3)
V3.3Dx_EDP: Skylake_TPS22993_U3_U4 (C59.2 R58.1 U3.1 V3.3Dx_EDP_[3.3V,0.75A].1), Skylake_LEDs_1 (U21.3)
V3.3Dx_SENSORS: Skylake_TPS22993_U3_U4 (C61.2 R61.1 U3.11 V3.3Dx_SENSORS_[3.3V,0.09A].1), Skylake_LEDs_1 (U23.3)
V3.3Dx_SSD: Skylake_TPS22993_U5_U6 (6 pins), Skylake_LEDs_2 (U31.3)
V3.3Dx_TOUCHSCREEN: Skylake_TPS22993_U5_U6 (C84.2 R81.1 U5.5 V3.3Dx_TOUCHSCREEN_[3.3V,0.20A].1), Skylake_LEDs_2 (U27.3)
V3.3Dx_USBSDIO: Skylake_TPS22993_U3_U4 (C58.2 R56.1 U3.5 V3.3Dx_USBSDIO_[3.3V,0.80A].1), Skylake_LEDs_1 (U20.3)
V3.3Dx_WIFI: Skylake_TPS22993_U5_U6 (5 pins), Skylake_LEDs_2 (U29.3)
V3.3M: Skylake_TPS22993_U3_U4 (C68.2 R68.1 U4.5 V3.3M_[3.3V,0.22A].1), Skylake_LEDs_2 (U24.3)
V3.3S: Skylake_TPS22993_U5_U6 (C94.2 R93.1 U6.5 V3.3S_[3.3V,0.03A].1), Skylake_LEDs_2 (U30.3)
V4(1.00V): Skylake_TPS22993_U7 (11 pins), Skylake_LEDs_2 (U36.3)

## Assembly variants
001: not fitted FID1 FID2 FID3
